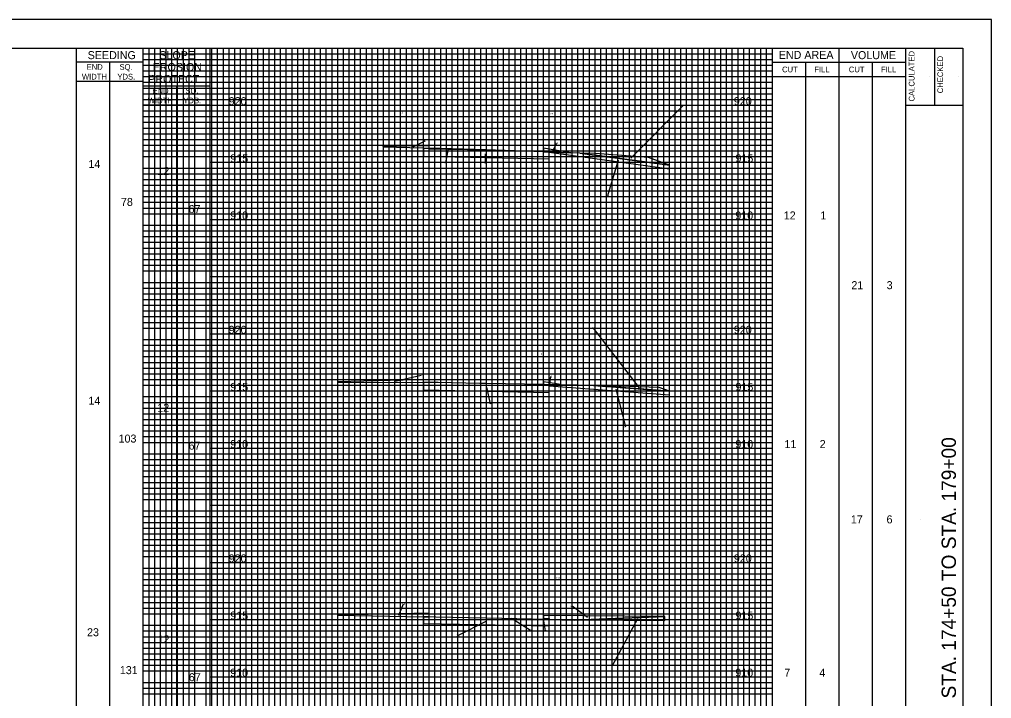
# Model space of a CAD drawing. Extents: x -73 to 160, y -2 to 1877.
# Drawn here: x 75 to 160, y 738.1 to 797.5 of the extents above; entities that cross this region are included whole.
import ezdxf

# ---------------------------------------------------------------- set-up
doc = ezdxf.new("R2010")
doc.units = 0
for name, color, linetype in [('DR_P_Flood_Boundary', 7, 'Continuous'), ('GK_Cells', 7, 'Continuous'), ('RD_X_Fence', 7, 'Continuous'), ('TX_X_5', 7, 'Continuous'), ('UT_P_Water_Cells', 7, 'Continuous'), ('XS_P_Pavt_Surface', 7, 'Continuous'), ('XS_X_Ground_Line', 7, 'Continuous')]:
    doc.layers.add(name, color=color, linetype=linetype)

msp = doc.modelspace()

# ---------------------------------------------------------------- linework, layer by layer
at = {"layer": 'DR_P_Flood_Boundary'}
for p, q in [((95.832, 690), (95.832, 795)), ((100.832, 690), (100.832, 795)), ((105.832, 690), (105.832, 795)), ((110.832, 690), (110.832, 795)), ((115.832, 690), (115.832, 795)), ((120.832, 690), (120.832, 795)), ((125.832, 690), (125.832, 795)), ((130.832, 690), (130.832, 795)), ((135.832, 690), (135.832, 795)), ((85.832, 790), (140.832, 790)), ((91.665, 785), (140.832, 785)), ((91.665, 780), (140.832, 780)), ((91.665, 775), (140.832, 775)), ((91.665, 770), (140.832, 770)), ((91.665, 765), (140.832, 765)), ((91.665, 760), (140.832, 760)), ((91.665, 755), (140.832, 755)), ((91.665, 750), (140.832, 750)), ((91.665, 745), (140.832, 745)), ((91.665, 740), (140.832, 740))]:
    msp.add_line(p, q, dxfattribs=at)
at = {"layer": 'GK_Cells'}
for p, q in [((152.5, 690), (152.5, 795)), ((155, 795), (155, 790)), ((152.5, 790), (157.5, 790))]:
    msp.add_line(p, q, dxfattribs=at)
msp.add_lwpolyline([(0, 795), (157.5, 795), (157.5, 690), (0, 690)], close=True, dxfattribs=at)
at = {"layer": 'RD_X_Fence'}
for p, q in [((128.463, 785.353), (133.032, 789.984)), ((110.832, 786.434), (106.768, 786.372)), ((109.438, 786.348), (110.487, 786.871)), ((110.832, 786.33), (110.832, 786.434)), ((121.627, 785.997), (121.989, 786.669)), ((110.332, 786.194), (110.332, 785.527)), ((110.332, 785.527), (121.332, 785.307)), ((110.832, 786.184), (115.832, 786.084)), ((115.832, 786.084), (110.834, 786.239)), ((112.5, 786.169), (112.268, 784.976)), ((115.736, 785.745), (115.716, 784.93)), ((120.832, 786.13), (120.83, 785.919)), ((123.218, 785.836), (120.832, 786.234)), ((120.832, 786.234), (120.832, 786.13)), ((120.832, 786.13), (120.832, 786.13)), ((121.332, 785.307), (121.332, 785.902)), ((123.218, 785.836), (121.332, 785.902)), ((121.332, 785.902), (131.832, 784.428)), ((123.994, 785.81), (123.218, 785.836)), ((123.994, 785.81), (131.832, 784.758)), ((131.832, 784.758), (123.994, 785.81)), ((127.353, 785.202), (126.418, 782.058)), ((131.832, 784.428), (131.832, 784.758)), ((129.217, 765.261), (125.197, 770.49)), ((110.832, 765.999), (102.832, 765.806)), ((107.853, 765.84), (110.12, 766.391)), ((121.375, 765.627), (121.453, 766.269)), ((102.832, 765.774), (110.332, 765.739)), ((110.332, 765.759), (110.332, 765.093)), ((110.332, 765.759), (110.832, 765.749)), ((110.332, 765.093), (121.332, 764.873)), ((115.832, 765.316), (116.151, 763.884)), ((122.329, 765.55), (120.832, 765.799)), ((121.332, 764.873), (121.332, 765.539)), ((122.328, 765.526), (121.332, 765.539)), ((121.332, 765.539), (121.332, 765.432)), ((121.332, 765.432), (131.832, 764.645)), ((125.202, 765.472), (122.328, 765.526)), ((125.202, 765.472), (131.832, 764.975)), ((129.21, 765.172), (125.202, 765.472)), ((127.133, 765.15), (127.982, 761.847)), ((131.832, 764.975), (129.21, 765.172)), ((131.832, 764.645), (131.832, 764.975)), ((108.164, 745.388), (108.578, 746.374)), ((110.832, 745.565), (102.832, 745.374)), ((110.831, 745.23), (110.832, 745.46)), ((110.832, 745.46), (110.832, 745.565)), ((124.667, 745.174), (123.334, 746.179)), ((102.832, 745.374), (110.332, 745.236)), ((110.332, 745.236), (110.332, 744.658)), ((110.332, 745.236), (110.831, 745.23)), ((110.332, 744.658), (121.332, 744.438)), ((115.791, 744.833), (113.359, 743.609)), ((118.024, 745.106), (119.684, 744.065)), ((120.797, 745.05), (120.962, 744.017)), ((131.426, 745.253), (120.832, 745.365)), ((120.832, 745.365), (120.832, 745.26)), ((120.832, 745.26), (120.832, 745.111)), ((120.832, 745.111), (121.332, 745.105)), ((121.332, 745.105), (121.332, 744.993)), ((121.332, 744.438), (121.332, 744.993)), ((131.426, 745.253), (124.263, 744.972)), ((124.263, 744.972), (131.426, 744.923)), ((129.038, 745.049), (126.822, 740.945)), ((131.426, 744.923), (131.426, 745.253))]:
    msp.add_line(p, q, dxfattribs=at)
for points in [[(106.768, 786.372), (106.768, 786.366)], [(106.768, 786.366), (110.334, 786.255), (110.83, 786.24)], [(110.83, 786.24), (110.832, 786.33)], [(116.275, 786.075), (115.832, 786.084), (110.832, 786.184), (110.332, 786.194)], [(110.834, 786.239), (110.832, 786.184)], [(121.332, 785.902), (121.33, 785.902), (120.83, 785.919), (116.626, 786.064), (116.275, 786.075)], [(120.83, 785.919), (121.332, 785.902), (123.218, 785.836)], [(120.832, 786.13), (120.832, 786.13)], [(131.832, 784.758), (130, 785.424), (125.338, 785.763), (123.994, 785.81)], [(110.832, 765.749), (110.832, 765.895), (110.832, 765.999)], [(102.832, 765.806), (102.832, 765.774)], [(121.332, 765.539), (120.832, 765.549), (115.831, 765.649), (115.263, 765.661), (111.619, 765.734), (110.832, 765.749), (110.332, 765.759)], [(110.332, 765.739), (110.332, 765.759)], [(120.832, 765.799), (120.832, 765.695), (120.832, 765.555)], [(120.832, 765.555), (120.833, 765.555), (121.333, 765.545), (122.328, 765.526)], [(122.328, 765.526), (122.329, 765.55)], [(131.832, 764.975), (130.928, 765.304), (127.414, 765.43), (125.202, 765.472)], [(121.332, 744.993), (119.837, 745.028), (115.833, 745.117), (111.403, 745.216), (110.831, 745.227), (110.332, 745.236)], [(121.332, 744.993), (123.49, 744.942), (131.426, 745.253)]]:
    msp.add_lwpolyline(points, dxfattribs=at)
at = {"layer": 'TX_X_5'}
msp.add_lwpolyline([(-10, 687.5), (160, 687.5), (160, 797.5), (-10, 797.5)], close=True, dxfattribs=at)
at = {"layer": 'UT_P_Water_Cells'}
for p, q in [((86.332, 690), (86.332, 795)), ((86.832, 690), (86.832, 795)), ((87.332, 690), (87.332, 795)), ((87.832, 690), (87.832, 795)), ((88.332, 690), (88.332, 795)), ((88.832, 690), (88.832, 795)), ((89.332, 690), (89.332, 795)), ((89.832, 690), (89.832, 795)), ((90.332, 690), (90.332, 795)), ((91.332, 690), (91.332, 795)), ((91.832, 690), (91.832, 795)), ((92.332, 690), (92.332, 795)), ((92.832, 690), (92.832, 795)), ((93.332, 690), (93.332, 795)), ((93.832, 690), (93.832, 795)), ((94.332, 690), (94.332, 795)), ((94.832, 690), (94.832, 795)), ((95.332, 690), (95.332, 795)), ((96.332, 690), (96.332, 795)), ((96.832, 690), (96.832, 795)), ((97.332, 690), (97.332, 795)), ((97.832, 690), (97.832, 795)), ((98.332, 690), (98.332, 795)), ((98.832, 690), (98.832, 795)), ((99.332, 690), (99.332, 795)), ((99.832, 690), (99.832, 795)), ((100.332, 690), (100.332, 795)), ((101.332, 690), (101.332, 795)), ((101.832, 690), (101.832, 795)), ((102.332, 690), (102.332, 795)), ((102.832, 690), (102.832, 795)), ((103.332, 690), (103.332, 795)), ((103.832, 690), (103.832, 795)), ((104.332, 690), (104.332, 795)), ((104.832, 690), (104.832, 795)), ((105.332, 690), (105.332, 795)), ((106.332, 690), (106.332, 795)), ((106.832, 690), (106.832, 795)), ((107.332, 690), (107.332, 795)), ((107.832, 690), (107.832, 795)), ((108.332, 690), (108.332, 795)), ((108.832, 690), (108.832, 795)), ((109.332, 690), (109.332, 795)), ((109.832, 690), (109.832, 795)), ((110.332, 690), (110.332, 795)), ((111.332, 690), (111.332, 795)), ((111.832, 690), (111.832, 795)), ((112.332, 690), (112.332, 795)), ((112.832, 690), (112.832, 795)), ((113.332, 690), (113.332, 795)), ((113.832, 690), (113.832, 795)), ((114.332, 690), (114.332, 795)), ((114.832, 690), (114.832, 795)), ((115.332, 690), (115.332, 795)), ((116.332, 690), (116.332, 795)), ((116.832, 690), (116.832, 795)), ((117.332, 690), (117.332, 795)), ((117.832, 690), (117.832, 795)), ((118.332, 690), (118.332, 795)), ((118.832, 690), (118.832, 795)), ((119.332, 690), (119.332, 795)), ((119.832, 690), (119.832, 795)), ((120.332, 690), (120.332, 795)), ((121.332, 690), (121.332, 795)), ((121.832, 690), (121.832, 795)), ((122.332, 690), (122.332, 795)), ((122.832, 690), (122.832, 795)), ((123.332, 690), (123.332, 795)), ((123.832, 690), (123.832, 795)), ((124.332, 690), (124.332, 795)), ((124.832, 690), (124.832, 795)), ((125.332, 690), (125.332, 795)), ((126.332, 690), (126.332, 795)), ((126.832, 690), (126.832, 795)), ((127.332, 690), (127.332, 795)), ((127.832, 690), (127.832, 795)), ((128.332, 690), (128.332, 795)), ((128.832, 690), (128.832, 795)), ((129.332, 690), (129.332, 795)), ((129.832, 690), (129.832, 795)), ((130.332, 690), (130.332, 795)), ((131.332, 690), (131.332, 795)), ((131.832, 690), (131.832, 795)), ((132.332, 690), (132.332, 795)), ((132.832, 690), (132.832, 795)), ((133.332, 690), (133.332, 795)), ((133.832, 690), (133.832, 795)), ((134.332, 690), (134.332, 795)), ((134.832, 690), (134.832, 795)), ((135.332, 690), (135.332, 795)), ((136.332, 690), (136.332, 795)), ((136.832, 690), (136.832, 795)), ((137.332, 690), (137.332, 795)), ((137.832, 690), (137.832, 795)), ((138.332, 690), (138.332, 795)), ((138.832, 690), (138.832, 795)), ((139.332, 690), (139.332, 795)), ((139.832, 690), (139.832, 795)), ((140.332, 690), (140.332, 795)), ((85.832, 794.5), (140.832, 794.5)), ((85.832, 794), (140.832, 794)), ((85.832, 793.5), (140.832, 793.5)), ((85.832, 793), (140.832, 793)), ((85.832, 792.5), (140.832, 792.5)), ((85.832, 792), (140.832, 792)), ((85.832, 791.5), (140.832, 791.5)), ((85.832, 791), (140.832, 791)), ((85.832, 790.5), (140.832, 790.5)), ((85.832, 789.5), (140.832, 789.5)), ((85.832, 789), (140.832, 789)), ((85.832, 788.5), (140.832, 788.5)), ((85.832, 788), (140.832, 788)), ((85.832, 787.5), (140.832, 787.5)), ((85.832, 787), (140.832, 787)), ((85.832, 786.5), (140.832, 786.5)), ((85.832, 786), (140.832, 786)), ((85.832, 785.5), (140.832, 785.5)), ((85.832, 784.5), (140.832, 784.5)), ((85.832, 784), (140.832, 784)), ((85.832, 783.5), (140.832, 783.5)), ((85.832, 783), (140.832, 783)), ((85.832, 782.5), (140.832, 782.5)), ((85.832, 782), (140.832, 782)), ((85.832, 781.5), (140.832, 781.5)), ((85.832, 781), (140.832, 781)), ((85.832, 780.5), (140.832, 780.5)), ((85.832, 779.5), (140.832, 779.5)), ((85.832, 779), (140.832, 779)), ((85.832, 778.5), (140.832, 778.5)), ((85.832, 778), (140.832, 778)), ((85.832, 777.5), (140.832, 777.5)), ((85.832, 777), (140.832, 777)), ((85.832, 776.5), (140.832, 776.5)), ((85.832, 776), (140.832, 776)), ((85.832, 775.5), (140.832, 775.5)), ((85.832, 774.5), (140.832, 774.5)), ((85.832, 774), (140.832, 774)), ((85.832, 773.5), (140.832, 773.5)), ((85.832, 773), (140.832, 773)), ((85.832, 772.5), (140.832, 772.5)), ((85.832, 772), (140.832, 772)), ((85.832, 771.5), (140.832, 771.5)), ((85.832, 771), (140.832, 771)), ((85.832, 770.5), (140.832, 770.5)), ((85.832, 769.5), (140.832, 769.5)), ((85.832, 769), (140.832, 769)), ((85.832, 768.5), (140.832, 768.5)), ((85.832, 768), (140.832, 768)), ((85.832, 767.5), (140.832, 767.5)), ((85.832, 767), (140.832, 767)), ((85.832, 766.5), (140.832, 766.5)), ((85.832, 766), (140.832, 766)), ((85.832, 765.5), (140.832, 765.5)), ((85.832, 764.5), (140.832, 764.5)), ((85.832, 764), (140.832, 764)), ((85.832, 763.5), (140.832, 763.5)), ((85.832, 763), (140.832, 763)), ((85.832, 762.5), (140.832, 762.5)), ((85.832, 762), (140.832, 762)), ((85.832, 761.5), (140.832, 761.5)), ((85.832, 761), (140.832, 761)), ((85.832, 760.5), (140.832, 760.5)), ((85.832, 759.5), (140.832, 759.5)), ((85.832, 759), (140.832, 759)), ((85.832, 758.5), (140.832, 758.5)), ((85.832, 758), (140.832, 758)), ((85.832, 757.5), (140.832, 757.5)), ((85.832, 757), (140.832, 757)), ((85.832, 756.5), (140.832, 756.5)), ((85.832, 756), (140.832, 756)), ((85.832, 755.5), (140.832, 755.5)), ((85.832, 754.5), (140.832, 754.5)), ((85.832, 754), (140.832, 754)), ((85.832, 753.5), (140.832, 753.5)), ((85.832, 753), (140.832, 753)), ((85.832, 752.5), (140.832, 752.5)), ((85.832, 752), (140.832, 752)), ((85.832, 751.5), (140.832, 751.5)), ((85.832, 751), (140.832, 751)), ((85.832, 750.5), (140.832, 750.5)), ((85.832, 749.5), (140.832, 749.5)), ((85.832, 749), (140.832, 749)), ((85.832, 748.5), (140.832, 748.5)), ((85.832, 748), (140.832, 748)), ((85.832, 747.5), (140.832, 747.5)), ((85.832, 747), (140.832, 747)), ((85.832, 746.5), (140.832, 746.5)), ((85.832, 746), (140.832, 746)), ((85.832, 745.5), (140.832, 745.5)), ((85.832, 744.5), (140.832, 744.5)), ((85.832, 744), (140.832, 744)), ((85.832, 743.5), (140.832, 743.5)), ((85.832, 743), (140.832, 743)), ((85.832, 742.5), (140.832, 742.5)), ((85.832, 742), (140.832, 742)), ((85.832, 741.5), (140.832, 741.5)), ((85.832, 741), (140.832, 741)), ((85.832, 740.5), (140.832, 740.5)), ((85.832, 739.5), (140.832, 739.5)), ((85.832, 739), (140.832, 739)), ((85.832, 738.5), (140.832, 738.5))]:
    msp.add_line(p, q, dxfattribs=at)
at = {"layer": 'XS_X_Ground_Line'}
for p, q in [((80, 690), (80, 795)), ((85.832, 690), (85.832, 795)), ((85.832, 690), (85.832, 795)), ((91.665, 690), (91.665, 795)), ((140.832, 690), (140.832, 795)), ((146.667, 690), (146.667, 795)), ((85.832, 793.75), (80, 793.75)), ((82.916, 690), (82.916, 793.75)), ((140.832, 793.75), (152.5, 793.75)), ((143.75, 690), (143.75, 793.75)), ((149.583, 690), (149.583, 793.75)), ((140.832, 792.5), (152.5, 792.5)), ((154.6, 792.518), (154.6, 792.518)), ((157.1, 792.518), (157.1, 792.518)), ((85.832, 792.083), (80, 792.083)), ((91.665, 791.667), (85.832, 791.667)), ((88.749, 690), (88.749, 791.667)), ((91.665, 790), (85.832, 790)), ((153.75, 753.75), (153.75, 753.75)), ((156.258, 753.75), (156.258, 753.75))]:
    msp.add_line(p, q, dxfattribs=at)

# ---------------------------------------------------------------- texts
at = {"layer": 'RD_X_Fence'}
for s, p in [('1.8', (132.903, 789.914)), ('8.0', (108.268, 789.297)), ('2.4', (121.403, 789.183)), ('0.4', (110.335, 786.801)), ('0.4', (121.837, 786.599)), ('0.1', (112.142, 784.906)), ('7.2', (115.572, 784.86)), ('2.8', (126.262, 781.988)), ('0.9', (125.031, 770.42)), ('8.0', (109.016, 768.543)), ('1.5', (120.589, 768.18)), ('1.2', (110.002, 766.321)), ('0.2', (121.301, 766.199)), ('7.3', (116.007, 763.814)), ('3.0', (127.819, 761.777)), ('8.0', (108.812, 747.864)), ('10.6', (121.907, 748.561)), ('1.4', (108.46, 746.304)), ('2.5', (123.189, 746.109)), ('0.3', (119.532, 743.995)), ('0.1', (120.836, 743.947)), ('6.3', (113.212, 743.539)), ('1.2', (126.692, 740.875))]:
    msp.add_text(s, height=0.14, dxfattribs=at).set_placement(p)
at = {"layer": 'XS_P_Pavt_Surface'}
for s, p in [('920', (93.298, 790)), ('920', (137.465, 790)), ('915', (93.441, 785)), ('915', (137.609, 785)), ('14', (81.031, 784.501)), ('12', (87.054, 783.882)), ('78', (83.875, 781.184)), ('67', (89.788, 780.565)), ('910', (93.43, 780)), ('910', (137.598, 780)), ('12', (141.829, 780)), ('1', (145.033, 780)), ('21', (147.743, 773.902)), ('3', (150.829, 773.902)), ('920', (93.298, 770)), ('920', (137.465, 770)), ('915', (93.441, 765)), ('915', (137.609, 765)), ('14', (81.031, 763.798)), ('12', (87.054, 763.179)), ('103', (83.666, 760.482)), ('67', (89.788, 759.862)), ('910', (93.43, 760)), ('910', (137.598, 760)), ('11', (141.892, 760)), ('2', (144.97, 760)), ('17', (147.696, 753.41)), ('6', (150.816, 753.41)), ('920', (93.298, 750)), ('920', (137.465, 750)), ('915', (93.441, 745)), ('915', (137.609, 745)), ('23', (80.91, 743.54)), ('12', (87.077, 742.92)), ('131', (83.776, 740.223)), ('910', (93.43, 740)), ('910', (137.598, 740)), ('7', (141.878, 740)), ('4', (144.94, 740)), ('67', (89.81, 739.604))]:
    msp.add_text(s, height=0.7, dxfattribs=at).set_placement(p)
at = {"layer": 'XS_X_Ground_Line'}
for s, height, p in [('SEEDING', 0.7, (80.964, 794.025)), ('SLOPE', 0.7, (87.228, 794.025)), ('END AREA', 0.7, (141.394, 794.047)), ('VOLUME', 0.7, (147.698, 794.025)), ('END', 0.5, (80.87, 793.092)), ('SQ.', 0.5, (83.748, 793.092)), ('EROSION', 0.7, (86.649, 792.983)), ('CUT', 0.5, (141.683, 792.875)), ('FILL', 0.5, (144.502, 792.875)), ('CUT', 0.5, (147.517, 792.875)), ('FILL', 0.5, (150.335, 792.875)), ('WIDTH', 0.5, (80.462, 792.242)), ('YDS.', 0.5, (83.563, 792.242)), ('PROTECT.', 0.7, (86.26, 791.942)), ('END', 0.5, (86.631, 791.008)), ('SQ.', 0.5, (89.51, 791.008)), ('WIDTH', 0.5, (86.224, 790.158)), ('YDS.', 0.5, (89.325, 790.158))]:
    msp.add_text(s, height=height, dxfattribs=at).set_placement(p)
for s, height, p in [('CALCULATED', 0.5, (153.262, 790.323)), ('CHECKED', 0.5, (155.762, 791.04)), ('STA. 174+50 TO STA. 179+00', 1.25, (156.883, 738.095))]:
    msp.add_text(s, height=height, rotation=90, dxfattribs=at).set_placement(p)

doc.saveas('drawing.dxf')
